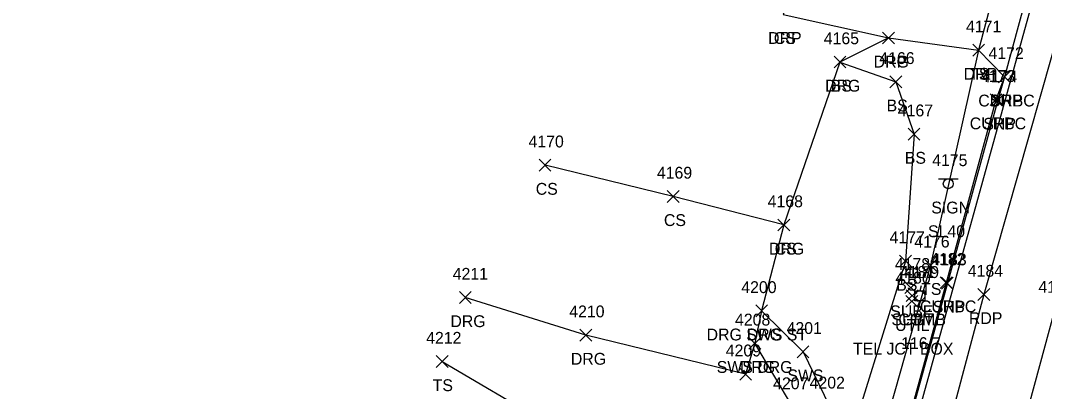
# Model space of a CAD drawing. Extents: x 1443912 to 1445411, y 621446 to 623693.
# Drawn here: x 1444817.3 to 1444990, y 623456.1 to 623518.7 of the extents above; entities that cross this region are included whole.
import ezdxf

# ---------------------------------------------------------------- set-up
doc = ezdxf.new("R2010")
doc.units = 0
for name, color, linetype in [('DCP', 7, 'Continuous'), ('L_A', 7, 'Continuous'), ('L_I', 7, 'Continuous'), ('L_TIC', 7, 'Continuous'), ('LELB', 7, 'Continuous'), ('P_A', 7, 'Continuous'), ('P_I', 7, 'Continuous'), ('P_TIC', 7, 'Continuous'), ('PET', 7, 'Continuous'), ('PRC', 7, 'Continuous'), ('PSP', 7, 'Continuous'), ('R_A', 7, 'Continuous'), ('R_I', 7, 'Continuous'), ('R_TIC', 7, 'Continuous'), ('RC', 7, 'Continuous'), ('RDG', 7, 'Continuous'), ('RDP', 7, 'Continuous'), ('RSW', 7, 'Continuous'), ('S_A', 7, 'Continuous'), ('S_C', 7, 'Continuous'), ('S_I', 7, 'Continuous'), ('SSGN', 7, 'Continuous'), ('U_A', 7, 'Continuous'), ('U_C', 7, 'Continuous'), ('U_I', 7, 'Continuous'), ('U_TIC', 7, 'Continuous'), ('UDEFAULT', 7, 'Continuous'), ('UP', 7, 'Continuous')]:
    doc.layers.add(name, color=color, linetype=linetype)

msp = doc.modelspace()

# ---------------------------------------------------------------- linework, layer by layer
at = {"layer": 'DCP'}
msp.add_lwpolyline([(1444991.54, 623534.89), (1444942.32, 623357.04)], dxfattribs=at)
at = {"layer": 'L_TIC'}
for points in [[(1444977.9, 623512.73), (1444979.9, 623514.73)], [(1444979.9, 623512.73), (1444977.9, 623514.73)], [(1444954.52, 623510.73), (1444956.52, 623512.73)], [(1444956.52, 623510.73), (1444954.52, 623512.73)], [(1444963.94, 623507.39), (1444965.94, 623509.39)], [(1444965.94, 623507.39), (1444963.94, 623509.39)], [(1444967.01, 623498.55), (1444969.01, 623500.55)], [(1444969.01, 623498.55), (1444967.01, 623500.55)], [(1444904.76, 623493.31), (1444906.76, 623495.31)], [(1444906.76, 623493.31), (1444904.76, 623495.31)], [(1444926.38, 623488.03), (1444928.38, 623490.03)], [(1444928.38, 623488.03), (1444926.38, 623490.03)], [(1444945.06, 623483.21), (1444947.06, 623485.21)], [(1444947.06, 623483.21), (1444945.06, 623485.21)], [(1444965.57, 623477.12), (1444967.57, 623479.12)], [(1444967.57, 623477.12), (1444965.57, 623479.12)], [(1444969.81, 623476.4), (1444971.81, 623478.4)], [(1444971.81, 623476.4), (1444969.81, 623478.4)], [(1444887.4, 623460.15), (1444889.4, 623462.15)], [(1444889.4, 623460.15), (1444887.4, 623462.15)]]:
    msp.add_lwpolyline(points, dxfattribs=at)
at = {"layer": 'LELB'}
for points in [[(1444999.5, 623624.29), (1445006.38, 623617.23), (1444999.2, 623587.78), (1444986.64, 623540.21), (1444984.08, 623533.25), (1444978.9, 623513.73), (1444970.81, 623477.4), (1444960.43, 623440.84), (1444953.7, 623417.64), (1444941.08, 623375.56)], [(1444955.52, 623511.73), (1444964.94, 623508.39), (1444968.01, 623499.55), (1444966.57, 623478.12), (1444955.62, 623442.73), (1444949.06, 623418.88), (1444941.08, 623375.56)], [(1444946.06, 623484.21), (1444927.38, 623489.03), (1444905.76, 623494.31)], [(1444888.4, 623461.15), (1444906.02, 623450.79), (1444929.21, 623447.93), (1444940.66, 623442.22), (1444939.45, 623421.19), (1444934.68, 623398.27)]]:
    msp.add_lwpolyline(points, dxfattribs=at)
at = {"layer": 'P_TIC'}
for points in [[(1444982.26, 623508.22), (1444984.26, 623510.22)], [(1444984.26, 623508.22), (1444982.26, 623510.22)], [(1444981.17, 623504.29), (1444983.17, 623506.29)], [(1444983.17, 623504.29), (1444981.17, 623506.29)], [(1444972.63, 623473.39), (1444974.63, 623475.39)], [(1444974.63, 623473.39), (1444972.63, 623475.39)], [(1444978.78, 623471.47), (1444980.78, 623473.47)], [(1444980.78, 623471.47), (1444978.78, 623473.47)]]:
    msp.add_lwpolyline(points, dxfattribs=at)
at = {"layer": 'PET'}
msp.add_lwpolyline([(1445036.7, 623677.7), (1445026.38, 623639.78), (1445008.65, 623576.15), (1444996.95, 623532.89), (1444979.78, 623472.47), (1444964.83, 623416.22), (1444955.71, 623382.54), (1444949.17, 623358.13), (1444939.29, 623323.43), (1444926.27, 623275.91), (1444914.83, 623235.04), (1444901.53, 623186.46), (1444892.14, 623152.69), (1444883.14, 623119.13), (1444870.13, 623073.23), (1444861.49, 623043.31), (1444850.84, 623006.82), (1444834.61, 622954.83), (1444817.28, 622898.33)], dxfattribs=at)
at = {"layer": 'PRC'}
msp.add_lwpolyline([(1445048.12, 623674.07), (1445038.05, 623635.88), (1445020.14, 623572.7), (1445008.5, 623529.11), (1444991.68, 623469.75), (1444976.21, 623412.44), (1444964.87, 623369.69), (1444950.64, 623318.47), (1444938.05, 623272.58), (1444925.39, 623227.3), (1444913.85, 623184.57), (1444903.74, 623148.67), (1444894.97, 623116.18), (1444881.8, 623068.92), (1444873.97, 623040.25), (1444864.1, 623005.34), (1444846.73, 622950.74), (1444829.37, 622896.11)], dxfattribs=at)
at = {"layer": 'PSP'}
msp.add_lwpolyline([(1445029.6, 623678.26), (1445021.68, 623649.55), (1445019.78, 623642.34), (1445019.32, 623640.93), (1445017.21, 623633.02), (1445017.08, 623631.73), (1445013.01, 623618.17), (1445011.68, 623612.99), (1445004.58, 623587.1), (1444990.43, 623535.38), (1444989.65, 623532.72), (1444983.26, 623509.22), (1444982.17, 623505.29), (1444973.63, 623474.39), (1444957.7, 623416.57), (1444946.06, 623374.16), (1444939.52, 623351.37), (1444938.45, 623347.36), (1444929.03, 623313.43)], dxfattribs=at)
at = {"layer": 'R_TIC'}
for points in [[(1444962.71, 623514.79), (1444964.71, 623516.79)], [(1444964.71, 623514.79), (1444962.71, 623516.79)], [(1444962.71, 623514.79), (1444964.71, 623516.79)], [(1444964.71, 623514.79), (1444962.71, 623516.79)], [(1444977.9, 623512.73), (1444979.9, 623514.73)], [(1444979.9, 623512.73), (1444977.9, 623514.73)], [(1444954.52, 623510.73), (1444956.52, 623512.73)], [(1444956.52, 623510.73), (1444954.52, 623512.73)], [(1444982.26, 623508.22), (1444984.26, 623510.22)], [(1444984.26, 623508.22), (1444982.26, 623510.22)], [(1444982.26, 623508.22), (1444984.26, 623510.22)], [(1444984.26, 623508.22), (1444982.26, 623510.22)], [(1444980.83, 623504.36), (1444982.83, 623506.36)], [(1444982.83, 623504.36), (1444980.83, 623506.36)], [(1444945.06, 623483.21), (1444947.06, 623485.21)], [(1444947.06, 623483.21), (1444945.06, 623485.21)], [(1444972.42, 623473.46), (1444974.42, 623475.46)], [(1444974.42, 623473.46), (1444972.42, 623475.46)], [(1444891.31, 623470.96), (1444893.31, 623472.96)], [(1444893.31, 623470.96), (1444891.31, 623472.96)], [(1444941.3, 623468.71), (1444943.3, 623470.71)], [(1444943.3, 623468.71), (1444941.3, 623470.71)], [(1444941.3, 623468.71), (1444943.3, 623470.71)], [(1444943.3, 623468.71), (1444941.3, 623470.71)], [(1444911.63, 623464.61), (1444913.63, 623466.61)], [(1444913.63, 623464.61), (1444911.63, 623466.61)], [(1444940.15, 623463.23), (1444942.15, 623465.23)], [(1444942.15, 623463.23), (1444940.15, 623465.23)], [(1444940.15, 623463.23), (1444942.15, 623465.23)], [(1444942.15, 623463.23), (1444940.15, 623465.23)], [(1444948.28, 623461.8), (1444950.28, 623463.8)], [(1444950.28, 623461.8), (1444948.28, 623463.8)], [(1444938.6, 623458.01), (1444940.6, 623460.01)], [(1444940.6, 623458.01), (1444938.6, 623460.01)]]:
    msp.add_lwpolyline(points, dxfattribs=at)
at = {"layer": 'RC'}
msp.add_lwpolyline([(1444983.26, 623509.22), (1444981.83, 623505.36), (1444973.42, 623474.46), (1444957.56, 623416.57), (1444945.85, 623374.13), (1444939.35, 623351.65), (1444938.45, 623347.36)], dxfattribs=at)
at = {"layer": 'RDG'}
msp.add_lwpolyline([(1444963.71, 623515.79), (1444955.52, 623511.73), (1444946.06, 623484.21), (1444942.3, 623469.71), (1444941.15, 623464.23), (1444939.6, 623459.01), (1444912.63, 623465.61), (1444892.31, 623471.96)], dxfattribs=at)
at = {"layer": 'RDP'}
msp.add_lwpolyline([(1444989.65, 623532.72), (1444984.08, 623533.25), (1444974.71, 623535.42), (1444952.54, 623540.59), (1444945.91, 623519.78), (1444963.71, 623515.79), (1444978.9, 623513.73), (1444983.26, 623509.22)], dxfattribs=at)
at = {"layer": 'RSW'}
msp.add_lwpolyline([(1444942.3, 623469.71), (1444949.28, 623462.8), (1444953.74, 623453.59), (1444953.94, 623443.54), (1444949.32, 623444.86), (1444947.57, 623453.47), (1444941.15, 623464.23)], dxfattribs=at)
at = {"layer": 'SSGN'}
for p, q in [((1444972.14, 623492.01), (1444975.47, 623492.01)), ((1444973.78, 623491.17), (1444973.78, 623491.17))]:
    msp.add_line(p, q, dxfattribs=at)
msp.add_circle((1444973.78, 623491.17), 0.833, dxfattribs=at)
at = {"layer": 'U_TIC'}
for points in [[(1444966.46, 623472.62), (1444968.46, 623474.62)], [(1444968.46, 623472.62), (1444966.46, 623474.62)], [(1444966.71, 623471.26), (1444968.71, 623473.26)], [(1444968.71, 623471.26), (1444966.71, 623473.26)]]:
    msp.add_lwpolyline(points, dxfattribs=at)
at = {"layer": 'UDEFAULT'}
for points in [[(1444966.65, 623470.31), (1444968.65, 623472.31)], [(1444968.65, 623470.31), (1444966.65, 623472.31)]]:
    msp.add_lwpolyline(points, dxfattribs=at)
at = {"layer": 'UP'}
for p, q in [((1444969.23, 623473.92), (1444968.98, 623473.09)), ((1444968.14, 623471.42), (1444968.14, 623473.09)), ((1444968.14, 623473.09), (1444969.81, 623473.09)), ((1444968.98, 623472.25), (1444968.98, 623472.25)), ((1444969.81, 623473.09), (1444969.81, 623471.42)), ((1444969.81, 623471.42), (1444968.14, 623471.42)), ((1444968.73, 623470.59), (1444968.98, 623471.42))]:
    msp.add_line(p, q, dxfattribs=at)
msp.add_circle((1444968.98, 623472.25), 0.833, dxfattribs=at)

# ---------------------------------------------------------------- texts
at = {"layer": 'L_A'}
for s, p in [('CS', (1444944.35, 623514.78)), ('TS', (1444977.31, 623508.73)), ('BS', (1444953.96, 623506.73)), ('BS', (1444963.38, 623503.39)), ('BS', (1444966.45, 623494.55)), ('CS', (1444904.2, 623489.31)), ('CS', (1444925.82, 623484.03)), ('CS', (1444944.5, 623479.21)), ('BS', (1444965.01, 623473.12)), ('TS', (1444969.21, 623472.4)), ('TS', (1444886.81, 623456.15))]:
    msp.add_text(s, height=2, dxfattribs=at).set_placement(p)
at = {"layer": 'L_I'}
for s, p in [('4171', (1444976.78, 623516.73)), ('4165', (1444952.78, 623514.73)), ('4166', (1444962.15, 623511.39)), ('4167', (1444965.27, 623502.55)), ('4170', (1444902.98, 623497.31)), ('4169', (1444924.63, 623492.03)), ('4168', (1444943.32, 623487.21)), ('4177', (1444963.88, 623481.12)), ('4176', (1444968.06, 623480.4)), ('4212', (1444885.71, 623464.15))]:
    msp.add_text(s, height=2, dxfattribs=at).set_placement(p)
at = {"layer": 'P_A'}
for s, p in [('SHP', (1444980.8, 623504.22)), ('SHP', (1444979.7, 623500.29)), ('SHP', (1444971.17, 623469.39)), ('RDP', (1444977.27, 623467.47))]:
    msp.add_text(s, height=2, dxfattribs=at).set_placement(p)
at = {"layer": 'P_I'}
for s, p in [('4172', (1444980.57, 623512.22)), ('4174', (1444979.47, 623508.29)), ('4183', (1444970.94, 623477.39)), ('4184', (1444977.08, 623475.47)), ('4185', (1444988.99, 623472.75))]:
    msp.add_text(s, height=2, dxfattribs=at).set_placement(p)
at = {"layer": 'R_A'}
for s, p in [('DRP', (1444943.4, 623514.78)), ('DRG', (1444961.2, 623510.79)), ('DRP', (1444961.2, 623510.79)), ('DRP', (1444976.39, 623508.73)), ('DRG', (1444953.01, 623506.73)), ('CURBC', (1444978.85, 623504.22)), ('DRP', (1444980.75, 623504.22)), ('CURBC', (1444977.41, 623500.36)), ('DRG', (1444943.55, 623479.21)), ('CURBC', (1444969, 623469.46)), ('DRG', (1444889.8, 623466.96)), ('DRG SWS ST', (1444933.02, 623464.71)), ('DRG', (1444939.79, 623464.71)), ('DRG', (1444910.12, 623460.61)), ('SWS DRG', (1444934.73, 623459.23)), ('DRG', (1444938.64, 623459.23)), ('SWS', (1444946.65, 623457.8))]:
    msp.add_text(s, height=2, dxfattribs=at).set_placement(p)
at = {"layer": 'R_I'}
for s, p in [('4171', (1444976.78, 623516.73)), ('4165', (1444952.78, 623514.73)), ('4172', (1444980.57, 623512.22)), ('4172', (1444980.57, 623512.22)), ('4173', (1444979.14, 623508.36)), ('4168', (1444943.32, 623487.21)), ('4182', (1444970.73, 623477.46)), ('4211', (1444890.19, 623474.96)), ('4200', (1444938.87, 623472.71)), ('4200', (1444938.87, 623472.71)), ('4210', (1444909.85, 623468.61)), ('4208', (1444937.81, 623467.23)), ('4208', (1444937.81, 623467.23)), ('4201', (1444946.51, 623465.8)), ('4209', (1444936.25, 623462.01)), ('4207', (1444944.24, 623456.47)), ('4202', (1444950.4, 623456.59))]:
    msp.add_text(s, height=2, dxfattribs=at).set_placement(p)
at = {"layer": 'S_A'}
msp.add_text('SIGN', height=2, dxfattribs=at).set_placement((1444970.92, 623486.15))
at = {"layer": 'S_C'}
msp.add_text('SL40', height=2, dxfattribs=at).set_placement((1444970.37, 623482.15))
at = {"layer": 'S_I'}
msp.add_text('4175', height=2, dxfattribs=at).set_placement((1444971.07, 623494.15))
at = {"layer": 'U_A'}
for s, p in [('SUBE', (1444964, 623468.62)), ('SUBT', (1444964.21, 623467.26)), ('UTIL', (1444964.82, 623466.31)), ('COMB', (1444965.36, 623467.25))]:
    msp.add_text(s, height=2, dxfattribs=at).set_placement(p)
at = {"layer": 'U_C'}
for s, p in [('116/7', (1444965.83, 623463.25)), ('TEL JCT BOX', (1444957.71, 623462.31))]:
    msp.add_text(s, height=2, dxfattribs=at).set_placement(p)
at = {"layer": 'U_I'}
for s, p in [('4178', (1444964.77, 623476.62)), ('4181', (1444965.59, 623475.26)), ('4179', (1444966.28, 623475.25)), ('4180', (1444964.87, 623474.31))]:
    msp.add_text(s, height=2, dxfattribs=at).set_placement(p)

doc.saveas('drawing.dxf')
